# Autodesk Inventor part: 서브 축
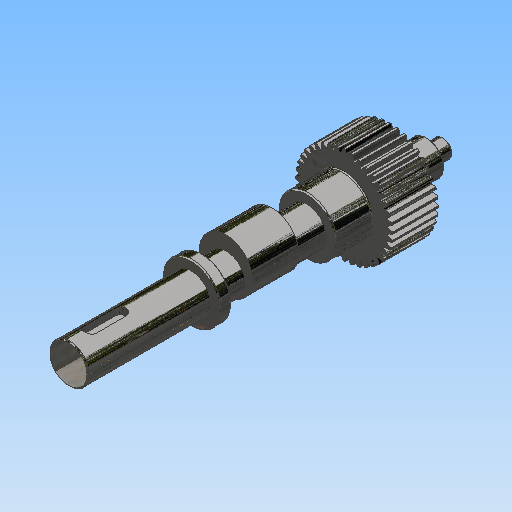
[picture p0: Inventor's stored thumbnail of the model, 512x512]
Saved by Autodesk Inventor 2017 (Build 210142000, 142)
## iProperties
Created: 2016-02
Part Number: 서브 축
Material: 강철, 연강
Document SubType Name: Modeling
Designer: mdu
Categories: <?xml version="1.0" encoding="UTF-16"?> <MemberInstance><Categories><FamilyTemplate><FamilyTemplateParameter ValueType="xs:double" Id="1" ObjectReferenceKey="da
Density: 7.86 g/cm^3
Mass: 506.173 g
Surface Area: 164.116 cm^2
Volume: 64.3986 cm^3
Appearance: 강철 - 광택
CustomPartVersion: 1
Author: mdu
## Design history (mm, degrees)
sketch "Sketch1"
  geometry: C1 r 21 at (0, 0)
  constraints: 1 centre point
  dimensions: "d0" = 42 diameter of C1 (= da_da)
extrude "Extrusion1" new body sketch "Sketch1" distance "d1" = 20 (= da_b); taper "d2" = 0 deg
workplane "Work Plane2"
feature "피치 지름" dims "d4" = 10, "d5" = 0
workplane "Work Plane8"
workplane "Work Plane9"
chamfer "모따기1" distance "d49" = 0.2; stored, may be unused: second distance "d50" = 2, angle "d51" = 45 deg
sketch "스케치3"
  geometry: C1 r 12.5 at (0, 0); 1 further point
  constraints: 1 centre point, 1 coincident
  dimensions: "d52" = 25 diameter of C1
extrude "돌출2" join sketch "스케치3" distance "d53" = 16; taper "d54" = 0 deg
sketch "스케치4"
  geometry: C1 r 8.5 at (0, 0); 1 further point
  constraints: 1 centre point, 1 coincident
  dimensions: "d55" = 17 diameter of C1
extrude "돌출3" join sketch "스케치4" distance "d56" = 103; taper "d57" = 0 deg
sketch "스케치5"
  geometry: C1 r 7.5 at (0, 0); 1 further point
  constraints: 1 centre point, 1 coincident
  dimensions: "d62" = 15 diameter of C1
extrude "돌출4" join sketch "스케치5" distance "d63" = 16; taper "d64" = 0 deg
sketch "스케치6"
  geometry: C1 r 4 at (0, 0); 1 further point
  constraints: 1 centre point, 1 coincident
  dimensions: "d65" = 8 diameter of C1
extrude "돌출5" join sketch "스케치6" distance "d66" = 7; taper "d67" = 0 deg
chamfer "모따기2" distance "d58" = 0.5; stored, may be unused: second distance "d59" = 2, angle "d60" = 45 deg
fillet "모깎기1" dims "d61" = 0.5
feature "스퍼 기어" dims "da_b" = 20, "da_d" = 40, "da_aw" = 31, "da_da" = 42, "da_df" = 37.5, "da_dw" = 40, angle "da_beta" = 0 deg, "da_lefttooth" = 0, "da_righttooth" = 0
node "작업 평면11"
sketch "스케치7"
  geometry: C1 r 8.5 at (0, 0) reference; C2 r 11.5 at (0, 3); 1 further point
  constraints: 1 centre point, 1 tangent, 1 vertical alignment
  dimensions: "d71" = 3 distance of C2.centre point (0, 0); "d72" = 23 diameter of C2 (derived)
extrude "돌출6" join sketch "스케치7" stored distance "d73" = 20; taper "d74" = 0 deg
node "작업 평면12"
sketch "스케치8"
  geometry: C1 r 12.5 at (0, 0) reference; 1 further point
extrude "돌출7" join sketch "스케치8" distance "d76" = 5; taper "d77" = 0 deg
chamfer "모따기3" distance "d78" = 0.5; stored, may be unused: second distance "d79" = 2, angle "d80" = 45 deg
sketch "스케치9"
  geometry: L1 (-8.5, 86)-(-8.5, 138.5) reference; L2 (-8, 139)-(8, 139) reference; L3 (0, 0)-(0, 139); L4 (-8.5, 115)-(0, 115); L5 (-8.5, 115)-(-8.5, 113.5); L6 (-7, 115)-(-8.5, 113.5)
  constraints: 8 end point, 4 point on line, 1 midpoint, 1 perpendicular
  dimensions: "d81" = 24 distance between parallel lines of L2 L4; "d82" = 45 deg angle of L6 L5; "d83" = 3 diameter of L5.end L4
revolve "회전1" sketch "스케치9" stored, may be unused: angle "d84" = 90 deg
sketch "스케치10"
  geometry: L1 (-8.5, 113.5)-(-7, 115) reference; L2 (-8.5, 116.5)-(-7, 115) reference; 2 further points
  constraints: 1 coincident
node "작업점1"
node "작업 평면14"
sketch "스케치11"
  geometry: L1 (8.5, 102.5)-(-8.5, 102.5) reference; L2 (0, 102.5)-(0, -36); L3 (-2.5, 93.5)-(-2.5, 80.5); L4 (2.5, 80.5)-(2.5, 93.5); L5 (-8, 103)-(8, 103) reference; A1 r 2.5 centre (0, 93.5) between (2.5, 93.5) and (-2.5, 93.5); A2 r 2.5 centre (0, 80.5) between (-2.5, 80.5) and (2.5, 80.5)
  constraints: 6 end point, 4 point on circle, 4 tangent, 2 centre point, 1 midpoint, 1 parallel, 1 perpendicular, 1 point on line, 1 vertical alignment
  dimensions: "d85" = 7 distance edge to line of A1 L5; "d86" = 18 dimension on A2 A1; "d87" = 5 distance between parallel lines of L3 L4
extrude "돌출8" cut sketch "스케치11" distance "d88" = 3; taper "d89" = 0 deg
body "Solid1"
sketch "Sketch2"
  geometry: C1 r 21 at (0, 0) reference; C2 r 20 at (0, 0)
  constraints: 1 centre point, 1 coincident
  dimensions: "d3" = 40 diameter of C2 (= da_dw)
body "Srf1"
other parameters: "d16" = 31 (= da_aw), "d17" = 0, "d34" = 4.5 deg (computed from da_z), "d39" = 0, "d41" = 0, "d43" = 31 (= da_aw), "d46" = 31 (= da_aw), "d47" = 0, "d48" = 0, "d68" = 25
